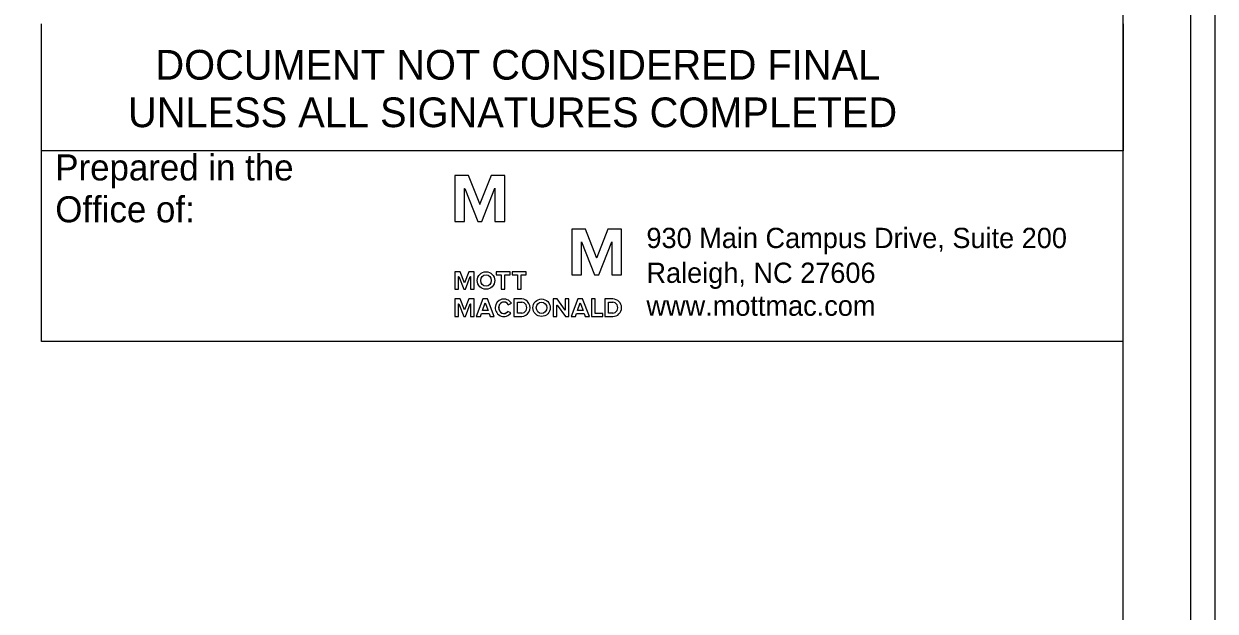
# Model space of a CAD drawing. Extents: x 1901670 to 1902225, y 193498 to 194278.
# Drawn here: x 1902112.21 to 1902134.24, y 194239.63 to 194250.51 of the extents above; entities that cross this region are included whole.
import ezdxf

# ---------------------------------------------------------------- set-up
doc = ezdxf.new("R2010")
doc.units = 0
for name, color, linetype in [('Old_Level_2', 7, 'Continuous'), ('Old_Level_42', 7, 'Continuous'), ('Sheet Border Standard 30in CELL', 7, 'Continuous'), ('Sheet Plot Border Inside CELL', 7, 'Continuous'), ('Sheet Plot Border Outside CELL', 7, 'Continuous'), ('Sheet Sticker Exception Certification CELL', 7, 'Continuous')]:
    doc.layers.add(name, color=color, linetype=linetype)

msp = doc.modelspace()

# ---------------------------------------------------------------- linework, layer by layer
at = {"layer": 'Old_Level_2'}
for p, q in [((1902120.437, 194247.699), (1902120.185, 194247.699)), ((1902120.185, 194247.699), (1902120.185, 194246.849)), ((1902120.642, 194247.174), (1902120.437, 194247.699)), ((1902120.853, 194247.699), (1902120.647, 194247.174)), ((1902121.105, 194247.699), (1902120.853, 194247.699)), ((1902121.105, 194246.849), (1902121.105, 194247.699)), ((1902120.364, 194246.849), (1902120.364, 194247.46)), ((1902120.364, 194247.46), (1902120.366, 194247.46)), ((1902120.366, 194247.46), (1902120.606, 194246.849)), ((1902120.684, 194246.849), (1902120.923, 194247.463)), ((1902120.923, 194247.463), (1902120.925, 194247.463)), ((1902120.925, 194247.463), (1902120.925, 194246.849)), ((1902120.642, 194247.166), (1902120.642, 194247.174)), ((1902120.647, 194247.166), (1902120.642, 194247.166)), ((1902120.647, 194247.174), (1902120.647, 194247.166)), ((1902120.185, 194246.849), (1902120.364, 194246.849)), ((1902120.606, 194246.849), (1902120.684, 194246.849)), ((1902120.925, 194246.849), (1902121.105, 194246.849)), ((1902122.598, 194246.709), (1902122.346, 194246.709)), ((1902122.346, 194246.709), (1902122.346, 194245.859)), ((1902122.803, 194246.184), (1902122.598, 194246.709)), ((1902123.014, 194246.709), (1902122.809, 194246.184)), ((1902123.266, 194246.709), (1902123.014, 194246.709)), ((1902123.266, 194245.859), (1902123.266, 194246.709)), ((1902122.525, 194245.859), (1902122.525, 194246.47)), ((1902122.525, 194246.47), (1902122.528, 194246.47)), ((1902122.528, 194246.47), (1902122.767, 194245.859)), ((1902122.845, 194245.859), (1902123.084, 194246.472)), ((1902123.084, 194246.472), (1902123.087, 194246.472)), ((1902123.087, 194246.472), (1902123.087, 194245.859)), ((1902122.803, 194246.176), (1902122.803, 194246.184)), ((1902122.809, 194246.176), (1902122.803, 194246.176)), ((1902122.809, 194246.184), (1902122.809, 194246.176)), ((1902120.281, 194245.919), (1902120.185, 194245.919)), ((1902120.185, 194245.919), (1902120.185, 194245.594)), ((1902120.252, 194245.594), (1902120.252, 194245.828)), ((1902120.252, 194245.828), (1902120.255, 194245.828)), ((1902120.252, 194245.828), (1902120.255, 194245.828)), ((1902120.255, 194245.828), (1902120.346, 194245.594)), ((1902120.361, 194245.716), (1902120.281, 194245.919)), ((1902120.442, 194245.919), (1902120.361, 194245.716)), ((1902120.377, 194245.594), (1902120.468, 194245.828)), ((1902120.538, 194245.919), (1902120.442, 194245.919)), ((1902120.468, 194245.828), (1902120.47, 194245.828)), ((1902120.468, 194245.828), (1902120.47, 194245.828)), ((1902120.468, 194245.828), (1902120.47, 194245.828)), ((1902120.47, 194245.828), (1902120.471, 194245.594)), ((1902120.538, 194245.594), (1902120.538, 194245.919)), ((1902120.538, 194245.594), (1902120.538, 194245.919)), ((1902122.346, 194245.859), (1902122.525, 194245.859)), ((1902122.767, 194245.859), (1902122.845, 194245.859)), ((1902123.087, 194245.859), (1902123.266, 194245.859)), ((1902120.185, 194245.594), (1902120.252, 194245.594)), ((1902120.346, 194245.594), (1902120.377, 194245.594)), ((1902120.471, 194245.594), (1902120.538, 194245.594)), ((1902120.281, 194245.414), (1902120.185, 194245.414)), ((1902120.185, 194245.414), (1902120.185, 194245.089)), ((1902120.252, 194245.089), (1902120.252, 194245.323)), ((1902120.252, 194245.323), (1902120.255, 194245.323)), ((1902120.255, 194245.323), (1902120.346, 194245.089)), ((1902120.361, 194245.211), (1902120.281, 194245.414)), ((1902120.442, 194245.414), (1902120.361, 194245.211)), ((1902120.377, 194245.089), (1902120.468, 194245.323)), ((1902120.538, 194245.414), (1902120.442, 194245.414)), ((1902120.468, 194245.323), (1902120.47, 194245.323)), ((1902120.47, 194245.323), (1902120.471, 194245.089)), ((1902120.538, 194245.089), (1902120.538, 194245.414)), ((1902121.172, 194245.308), (1902121.229, 194245.335)), ((1902121.172, 194245.308), (1902121.229, 194245.334)), ((1902121.422, 194245.414), (1902121.274, 194245.414)), ((1902121.274, 194245.414), (1902121.274, 194245.246)), ((1902121.341, 194245.152), (1902121.341, 194245.354)), ((1902121.341, 194245.354), (1902121.422, 194245.354)), ((1902122.955, 194245.414), (1902122.955, 194245.414)), ((1902123.104, 194245.414), (1902122.955, 194245.414)), ((1902122.955, 194245.414), (1902122.955, 194245.246)), ((1902123.023, 194245.152), (1902123.023, 194245.354)), ((1902123.023, 194245.354), (1902123.104, 194245.354)), ((1902123.104, 194245.352), (1902123.104, 194245.352)), ((1902120.185, 194245.089), (1902120.252, 194245.089)), ((1902120.346, 194245.089), (1902120.377, 194245.089)), ((1902120.471, 194245.089), (1902120.538, 194245.089)), ((1902121.221, 194245.156), (1902121.164, 194245.184)), ((1902121.221, 194245.156), (1902121.164, 194245.184)), ((1902121.274, 194245.246), (1902121.274, 194245.089)), ((1902121.274, 194245.089), (1902121.422, 194245.089)), ((1902121.422, 194245.152), (1902121.341, 194245.152)), ((1902122.955, 194245.246), (1902122.955, 194245.089)), ((1902122.955, 194245.089), (1902123.104, 194245.089)), ((1902123.104, 194245.152), (1902123.023, 194245.152))]:
    msp.add_line(p, q, dxfattribs=at)
for points in [[(1902120.946, 194245.859), (1902121.04, 194245.859), (1902121.04, 194245.594), (1902121.11, 194245.594), (1902121.11, 194245.859), (1902121.204, 194245.859), (1902121.204, 194245.919), (1902120.946, 194245.919), (1902120.946, 194245.859)], [(1902121.245, 194245.859), (1902121.339, 194245.859), (1902121.339, 194245.594), (1902121.409, 194245.594), (1902121.409, 194245.859), (1902121.502, 194245.859), (1902121.502, 194245.919), (1902121.245, 194245.919), (1902121.245, 194245.859)], [(1902120.577, 194245.089), (1902120.655, 194245.089), (1902120.676, 194245.144), (1902120.816, 194245.144), (1902120.837, 194245.089), (1902120.912, 194245.089), (1902120.788, 194245.414), (1902120.702, 194245.414), (1902120.577, 194245.089)], [(1902120.694, 194245.204), (1902120.746, 194245.344), (1902120.798, 194245.204), (1902120.694, 194245.204)], [(1902122.069, 194245.3), (1902122.072, 194245.3), (1902122.228, 194245.089), (1902122.293, 194245.089), (1902122.293, 194245.414), (1902122.225, 194245.414), (1902122.225, 194245.209), (1902122.072, 194245.414), (1902122.004, 194245.414), (1902122.004, 194245.089), (1902122.069, 194245.089), (1902122.069, 194245.3)], [(1902122.334, 194245.089), (1902122.412, 194245.089), (1902122.433, 194245.144), (1902122.573, 194245.144), (1902122.594, 194245.089), (1902122.67, 194245.089), (1902122.545, 194245.414), (1902122.459, 194245.414), (1902122.334, 194245.089)], [(1902122.451, 194245.204), (1902122.503, 194245.344), (1902122.555, 194245.204), (1902122.451, 194245.204)], [(1902122.917, 194245.089), (1902122.917, 194245.147), (1902122.776, 194245.147), (1902122.776, 194245.414), (1902122.709, 194245.414), (1902122.709, 194245.089), (1902122.917, 194245.089)], [(1902122.917, 194245.089), (1902122.917, 194245.147), (1902122.776, 194245.147), (1902122.776, 194245.414), (1902122.709, 194245.414), (1902122.709, 194245.089), (1902122.917, 194245.09), (1902122.917, 194245.147)]]:
    msp.add_lwpolyline(points, dxfattribs=at)
msp.add_arc((1902123.104, 194245.252), 0.162, 270, 90, dxfattribs=at)
for centre, major_axis, ratio in [((1902120.759, 194245.756), (0, 0.162), 0.993118), ((1902120.759, 194245.756), (0, 0.106), 0.916103), ((1902121.786, 194245.252), (0, 0.162), 0.993118), ((1902121.786, 194245.252), (0, 0.106), 0.916103)]:
    msp.add_ellipse(centre, major_axis=major_axis, ratio=ratio, dxfattribs=at)
for centre, major_axis, ratio, start_param, end_param in [((1902121.09, 194245.252), (0, 0.162), 0.993118, 5.246647, 10.366427), ((1902121.09, 194245.252), (0, 0.162), 0.993118, 5.246647, 10.366427), ((1902121.09, 194245.252), (0, 0.106), 0.916103, 5.276876, 9.424778), ((1902121.09, 194245.252), (0, 0.106), 0.916103, 5.276876, 10.296021), ((1902121.422, 194245.252), (0, -0.162), 0.930276, 0, 3.141593), ((1902121.422, 194245.253), (0, -0.101), 0.900832, 0, 3.141593), ((1902123.104, 194245.253), (0, -0.101), 0.900832, 0, 3.141593), ((1902121.09, 194245.252), (0, 0.106), 0.916103, 3.141593, 4.012835)]:
    msp.add_ellipse(centre, major_axis=major_axis, ratio=ratio, start_param=start_param, end_param=end_param, dxfattribs=at)
at = {"layer": 'Old_Level_42'}
msp.add_lwpolyline([(1902132.544, 194244.629), (1902112.539, 194244.629), (1902112.539, 194248.159)], dxfattribs=at)
at = {"layer": 'Sheet Border Standard 30in CELL'}
msp.add_lwpolyline([(1902132.544, 194265.514), (1901982.544, 194265.514), (1901982.544, 194160.514), (1902132.544, 194160.514)], close=True, dxfattribs=at)
at = {"layer": 'Sheet Plot Border Inside CELL'}
msp.add_lwpolyline([(1902133.794, 194265.769), (1901967.144, 194265.769), (1901967.144, 194160.259), (1902133.794, 194160.259)], close=True, dxfattribs=at)
at = {"layer": 'Sheet Plot Border Outside CELL'}
msp.add_lwpolyline([(1902134.244, 194268.014), (1901965.844, 194268.014), (1901965.844, 194158.014), (1902134.244, 194158.014)], close=True, dxfattribs=at)
at = {"layer": 'Sheet Sticker Exception Certification CELL'}
for p, q in [((1902112.539, 194248.159), (1902112.539, 194250.509)), ((1902132.542, 194250.508), (1902132.542, 194248.158)), ((1902132.542, 194248.159), (1902112.539, 194248.159))]:
    msp.add_line(p, q, dxfattribs=at)

# ---------------------------------------------------------------- texts
at = {"layer": 'Old_Level_2'}
for s, height, p in [('Prepared in the ', 0.48186, (1902112.794, 194247.609)), ('Office of:', 0.4819, (1902112.794, 194246.834))]:
    msp.add_text(s, height=height, dxfattribs=at).set_placement(p)
for s, p in [('930 Main Campus Drive, Suite 200', (1902123.726, 194246.357)), ('Raleigh, NC 27606', (1902123.726, 194245.712)), ('www.mottmac.com ', (1902123.726, 194245.103))]:
    msp.add_text(s, height=0.375, rotation=360, dxfattribs=at).set_placement(p)
at = {"layer": 'Sheet Sticker Exception Certification CELL'}
for s, p in [('DOCUMENT NOT CONSIDERED FINAL', (1902114.646, 194249.475)), ('UNLESS ALL SIGNATURES COMPLETED', (1902114.139, 194248.595))]:
    msp.add_text(s, height=0.55, dxfattribs=at).set_placement(p)

doc.saveas('drawing.dxf')
